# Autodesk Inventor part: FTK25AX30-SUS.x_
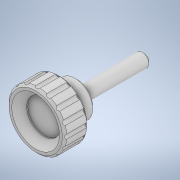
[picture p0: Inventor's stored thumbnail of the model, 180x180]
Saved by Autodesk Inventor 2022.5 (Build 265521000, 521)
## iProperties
Created: 2023-10
Part Number: FTK25AX30-SUS.x_
Material: 一般
Document SubType Name: Modeling
Designer: ImaoCorp
Density: 1 g/cm^3
Appearance: 既定
Sending System: SOLIDWORKS 2021-2021301
MC: AMD64
MC_MODEL: Intel64 Family 6 Model 60 Stepping 3, GenuineIntel
OS: Windows_NT
FRU: Parasolid Version 32.1, build 255,  1- 1-2021
FORMAT: text
GUISE: transmit
KEY: FTK25AX30-SUS
FILE: FTK25AX30-SUS.x_t
DATE: Tue Oct 17 11:07:41 2023
Author: ImaoCorp
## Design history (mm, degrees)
feature "Base1"
node "ソリッド1"
